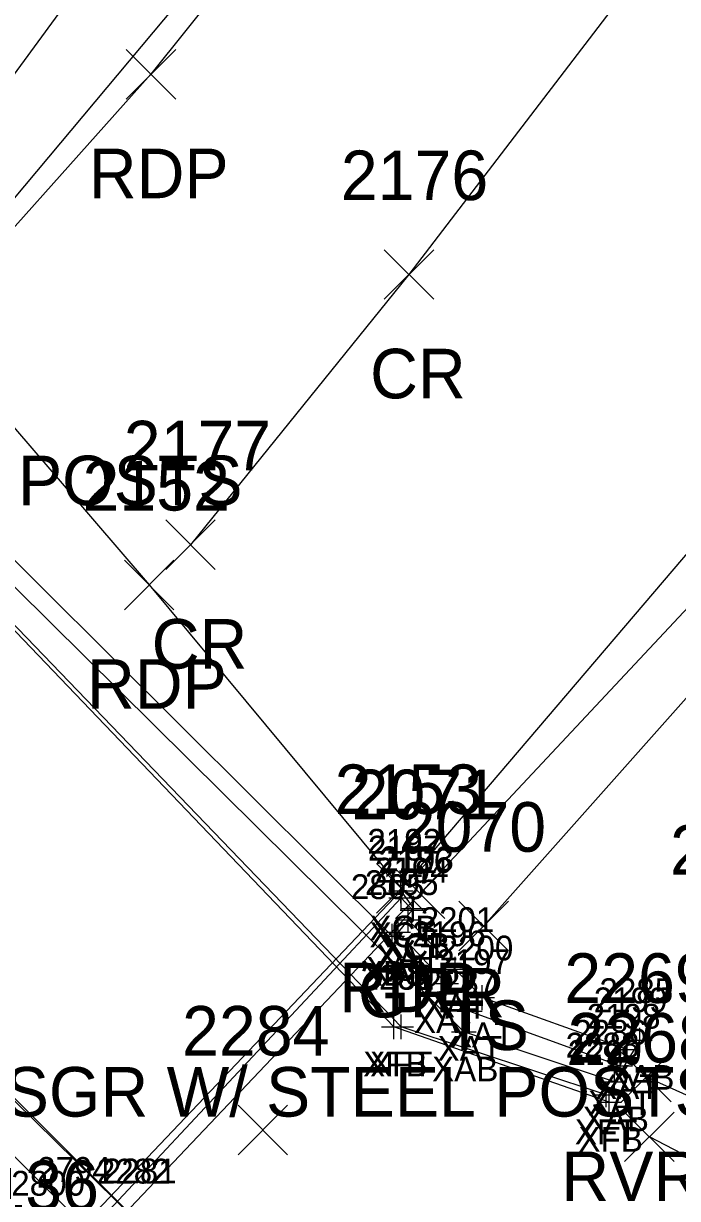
# Model space of a CAD drawing. Extents: x 1633660 to 1636532, y 388643 to 392631.
# Drawn here: x 1634763.61 to 1634790.01, y 389221.92 to 389269.34 of the extents above; entities that cross this region are included whole.
import ezdxf

# ---------------------------------------------------------------- set-up
doc = ezdxf.new("R2010")
doc.units = 0
for name, color, linetype in [('B_A', 7, 'Continuous'), ('B_I', 7, 'Continuous'), ('B_TIC', 7, 'Continuous'), ('BDC', 7, 'Continuous'), ('BFT', 7, 'Continuous'), ('BSE', 7, 'Continuous'), ('BSUBM', 7, 'Continuous'), ('L_A', 7, 'Continuous'), ('L_I', 7, 'Continuous'), ('L_TIC', 7, 'Continuous'), ('LAWE', 7, 'Continuous'), ('LELB', 7, 'Continuous'), ('P_A', 7, 'Continuous'), ('P_I', 7, 'Continuous'), ('P_TIC', 7, 'Continuous'), ('PET', 7, 'Continuous'), ('PRC', 7, 'Continuous'), ('R_A', 7, 'Continuous'), ('R_C', 7, 'Continuous'), ('R_I', 7, 'Continuous'), ('R_TIC', 7, 'Continuous'), ('RGR', 7, 'Continuous')]:
    doc.layers.add(name, color=color, linetype=linetype)

msp = doc.modelspace()

# ---------------------------------------------------------------- linework, layer by layer
at = {"layer": 'B_TIC'}
for p, q in [((1634778.841, 389234.337), (1634778.916, 389234.337)), ((1634778.862, 389234.061), (1634778.937, 389234.061)), ((1634779.315, 389233.554), (1634779.391, 389233.554)), ((1634779.356, 389233.631), (1634779.431, 389233.631)), ((1634779.145, 389233.172), (1634779.221, 389233.172)), ((1634778.496, 389232.505), (1634778.572, 389232.505)), ((1634778.738, 389232.666), (1634778.813, 389232.666)), ((1634781.031, 389231.176), (1634781.107, 389231.176)), ((1634780.673, 389230.603), (1634780.749, 389230.603)), ((1634782.122, 389230.029), (1634782.198, 389230.029)), ((1634781.623, 389229.48), (1634781.699, 389229.48)), ((1634778.565, 389228.852), (1634778.641, 389228.852)), ((1634778.856, 389228.848), (1634778.932, 389228.848)), ((1634781.387, 389228.651), (1634781.462, 389228.651)), ((1634788.493, 389228.309), (1634788.568, 389228.309)), ((1634787.983, 389227.938), (1634788.059, 389227.938)), ((1634787.698, 389227.277), (1634787.774, 389227.277)), ((1634787.465, 389226.63), (1634787.54, 389226.63)), ((1634787.127, 389226.112), (1634787.203, 389226.112)), ((1634787.255, 389225.814), (1634787.33, 389225.814))]:
    msp.add_line(p, q, dxfattribs=at)
for points in [[(1634778.837, 389233.837), (1634778.837, 389234.837)], [(1634778.858, 389233.56), (1634778.858, 389234.561)], [(1634778.337, 389234.337), (1634779.337, 389234.337)], [(1634778.358, 389234.061), (1634779.358, 389234.061)], [(1634779.312, 389233.054), (1634779.312, 389234.054)], [(1634779.352, 389233.131), (1634779.352, 389234.131)], [(1634778.812, 389233.554), (1634779.812, 389233.554)], [(1634778.852, 389233.631), (1634779.852, 389233.631)], [(1634779.142, 389232.672), (1634779.142, 389233.672)], [(1634778.493, 389232.005), (1634778.493, 389233.005)], [(1634778.642, 389233.172), (1634779.642, 389233.172)], [(1634778.734, 389232.166), (1634778.734, 389233.166)], [(1634777.993, 389232.505), (1634778.993, 389232.505)], [(1634778.234, 389232.666), (1634779.234, 389232.666)], [(1634781.028, 389230.676), (1634781.028, 389231.676)], [(1634780.528, 389231.176), (1634781.528, 389231.176)], [(1634780.67, 389230.103), (1634780.67, 389231.103)], [(1634780.17, 389230.603), (1634781.17, 389230.603)], [(1634782.119, 389229.529), (1634782.119, 389230.529)], [(1634781.619, 389230.029), (1634782.619, 389230.029)], [(1634781.62, 389228.98), (1634781.62, 389229.98)], [(1634778.562, 389228.352), (1634778.562, 389229.352)], [(1634778.853, 389228.348), (1634778.853, 389229.348)], [(1634781.12, 389229.48), (1634782.12, 389229.48)], [(1634778.062, 389228.852), (1634779.062, 389228.852)], [(1634778.353, 389228.848), (1634779.353, 389228.848)], [(1634781.383, 389228.151), (1634781.383, 389229.151)], [(1634788.489, 389227.809), (1634788.489, 389228.809)], [(1634780.883, 389228.651), (1634781.883, 389228.651)], [(1634787.98, 389227.438), (1634787.98, 389228.438)], [(1634787.989, 389228.309), (1634788.989, 389228.309)], [(1634787.48, 389227.938), (1634788.48, 389227.938)], [(1634787.695, 389226.777), (1634787.695, 389227.777)], [(1634787.195, 389227.277), (1634788.195, 389227.277)], [(1634787.461, 389226.13), (1634787.461, 389227.13)], [(1634786.961, 389226.63), (1634787.961, 389226.63)], [(1634787.124, 389225.612), (1634787.124, 389226.612)], [(1634786.624, 389226.112), (1634787.624, 389226.112)], [(1634787.251, 389225.314), (1634787.251, 389226.314)], [(1634786.751, 389225.814), (1634787.751, 389225.814)]]:
    msp.add_lwpolyline(points, dxfattribs=at)
at = {"layer": 'BDC'}
for points in [[(1634764.194, 389217.752), (1634763.74, 389218.447), (1634778.837, 389234.337), (1634779.352, 389233.631)], [(1634779.312, 389233.554), (1634778.858, 389234.061), (1634764.163, 389218.344), (1634764.455, 389217.898)], [(1634764.455, 389217.898), (1634779.312, 389233.554)]]:
    msp.add_lwpolyline(points, dxfattribs=at)
at = {"layer": 'BFT'}
for points in [[(1634787.251, 389225.814), (1634778.562, 389228.852), (1634756.719, 389251.654), (1634754.734, 389261.584)], [(1634787.124, 389226.112), (1634778.853, 389228.848), (1634756.842, 389251.699), (1634755.357, 389261.733)], [(1634747.068, 389242.136), (1634768.198, 389221.026)], [(1634746.993, 389241.835), (1634768.161, 389221.033)]]:
    msp.add_lwpolyline(points, dxfattribs=at)
at = {"layer": 'BSE'}
msp.add_lwpolyline([(1634757.888, 389256.912), (1634758.598, 389252.274), (1634778.493, 389232.505)], dxfattribs=at)
at = {"layer": 'BSUBM'}
for points in [[(1634788.489, 389228.309), (1634787.461, 389226.63), (1634781.383, 389228.651), (1634757.708, 389252.066), (1634756.355, 389261.792), (1634750.726, 389271.945), (1634751.561, 389272.556)], [(1634728.916, 389249.02), (1634729.836, 389250.104), (1634742.136, 389242.622), (1634746.673, 389240.04), (1634765.788, 389221.095)], [(1634779.142, 389233.172), (1634778.734, 389232.666), (1634780.67, 389230.603), (1634781.62, 389229.48), (1634787.695, 389227.277), (1634787.98, 389227.938), (1634782.119, 389230.029), (1634781.028, 389231.176)], [(1634781.028, 389231.176), (1634779.142, 389233.172)]]:
    msp.add_lwpolyline(points, dxfattribs=at)
at = {"layer": 'L_TIC'}
for points in [[(1634781.182, 389231.916), (1634783.182, 389233.916)], [(1634783.182, 389231.916), (1634781.182, 389233.916)], [(1634787.756, 389225.818), (1634789.756, 389227.818)], [(1634789.756, 389225.818), (1634787.756, 389227.818)], [(1634772.269, 389223.69), (1634774.269, 389225.69)], [(1634774.269, 389223.69), (1634772.269, 389225.69)], [(1634787.875, 389223.41), (1634789.875, 389225.41)], [(1634789.875, 389223.41), (1634787.875, 389225.41)]]:
    msp.add_lwpolyline(points, dxfattribs=at)
at = {"layer": 'LAWE'}
msp.add_lwpolyline([(1634485.266, 388945.868), (1634504.196, 388941.237), (1634525.532, 388940.734), (1634548.507, 388932.941), (1634584.664, 388919.999), (1634598.752, 388914.409), (1634618.803, 388928.878), (1634638.301, 388944.913), (1634660.99, 388957.079), (1634677.576, 388983.238), (1634696.949, 389006.397), (1634707.364, 389033.308), (1634727.928, 389056.715), (1634749.887, 389078.696), (1634762.92, 389095.064), (1634797.897, 389102.54), (1634816.332, 389112.037), (1634824.178, 389130.773), (1634824.184, 389150.648), (1634818.446, 389174.952), (1634815.049, 389205.919), (1634802.108, 389220.823), (1634788.756, 389226.818)], dxfattribs=at)
at = {"layer": 'LELB'}
for points in [[(1634760.285, 389263.273), (1634777.705, 389287.048), (1634795.737, 389315.603), (1634812.364, 389341.102), (1634834.547, 389376.799), (1634859.6, 389420.587), (1634884.98, 389473.483), (1634914.697, 389519.937)], [(1634830.021, 389262.502), (1634817.023, 389265.015), (1634802.099, 389255.301), (1634782.182, 389232.916)], [(1634633.695, 388947.021), (1634652.585, 388956.595), (1634671.201, 388984.135), (1634685.401, 389000.206), (1634693.628, 389014.81), (1634704.343, 389035.4), (1634725.63, 389062.246), (1634746.904, 389081.237), (1634759.284, 389096.885), (1634788.685, 389102.007), (1634810.124, 389114.596), (1634818.922, 389123.639), (1634818.088, 389148.686), (1634815.048, 389173.408), (1634811.187, 389202.43), (1634801.315, 389217.947), (1634788.875, 389224.41)]]:
    msp.add_lwpolyline(points, dxfattribs=at)
at = {"layer": 'P_TIC'}
for points in [[(1634767.754, 389266.285), (1634769.754, 389268.285)], [(1634769.754, 389266.285), (1634767.754, 389268.285)], [(1634778.167, 389258.209), (1634780.167, 389260.209)], [(1634780.167, 389258.209), (1634778.167, 389260.209)], [(1634769.349, 389247.304), (1634771.349, 389249.304)], [(1634771.349, 389247.304), (1634769.349, 389249.304)], [(1634767.683, 389245.682), (1634769.683, 389247.682)], [(1634769.683, 389245.682), (1634767.683, 389247.682)], [(1634777.862, 389233.437), (1634779.862, 389235.437)], [(1634779.862, 389233.437), (1634777.862, 389235.437)]]:
    msp.add_lwpolyline(points, dxfattribs=at)
at = {"layer": 'PET'}
for points in [[(1634921.002, 389515.03), (1634899.802, 389480.53), (1634874.189, 389437.174), (1634846.922, 389390.201), (1634820.403, 389343.783), (1634802.56, 389312.32), (1634782.667, 389284.651), (1634768.754, 389267.285)], [(1634759.683, 389257.144), (1634768.683, 389246.682), (1634778.862, 389234.437), (1634802.838, 389262.519), (1634835.45, 389312.997), (1634837.672, 389319.49), (1634869.562, 389375.262), (1634896.662, 389421.501), (1634916.947, 389456.153), (1634943.654, 389500.194)], [(1634768.754, 389267.285), (1634759.683, 389257.144)]]:
    msp.add_lwpolyline(points, dxfattribs=at)
at = {"layer": 'PRC'}
msp.add_lwpolyline([(1634932.003, 389507.764), (1634911.044, 389472.797), (1634886.741, 389431.158), (1634857.717, 389381.065), (1634832.11, 389337.094), (1634812.294, 389305.303), (1634793.243, 389277.601), (1634779.167, 389259.209), (1634770.349, 389248.304)], dxfattribs=at)
at = {"layer": 'R_TIC'}
for points in [[(1634778.621, 389233.228), (1634780.621, 389235.228)], [(1634780.621, 389233.228), (1634778.621, 389235.228)]]:
    msp.add_lwpolyline(points, dxfattribs=at)
at = {"layer": 'RGR'}
for points in [[(1634760.391, 389258.897), (1634777.727, 389279.589), (1634802.798, 389315.456), (1634808.813, 389326.626), (1634809.837, 389333.481)], [(1634779.621, 389234.228), (1634797.348, 389253.149), (1634807.413, 389262.179)]]:
    msp.add_lwpolyline(points, dxfattribs=at)

# ---------------------------------------------------------------- texts
at = {"layer": 'B_A'}
for s, p in [('XCB', (1634777.573, 389232.337)), ('XCT', (1634777.579, 389232.061)), ('XCT', (1634778.032, 389231.554)), ('XCB', (1634778.088, 389231.631)), ('XAT', (1634777.847, 389231.172)), ('XAT', (1634777.439, 389230.666)), ('XBS', (1634777.233, 389230.505)), ('XAT', (1634779.733, 389229.176)), ('XAT', (1634779.374, 389228.603)), ('XAT', (1634780.824, 389228.029)), ('XAT', (1634780.324, 389227.48)), ('XFB', (1634777.321, 389226.852)), ('XFT', (1634777.597, 389226.848)), ('XAB', (1634780.104, 389226.651)), ('XAB', (1634787.21, 389226.309)), ('XAT', (1634786.685, 389225.938)), ('XAT', (1634786.399, 389225.277)), ('XAB', (1634786.182, 389224.63)), ('XFT', (1634785.868, 389224.112)), ('XFB', (1634786.011, 389223.814))]:
    msp.add_text(s, height=1, dxfattribs=at).set_placement(p)
at = {"layer": 'B_I'}
for s, p in [('2192', (1634777.491, 389235.837)), ('2187', (1634777.512, 389235.561)), ('2186', (1634777.938, 389235.054)), ('2193', (1634778.006, 389235.131)), ('2194', (1634777.795, 389234.672)), ('2805', (1634776.823, 389234.005)), ('2195', (1634777.388, 389234.166)), ('2201', (1634779.642, 389232.676)), ('2196', (1634779.296, 389232.103)), ('2200', (1634780.406, 389231.529)), ('2197', (1634780.273, 389230.98)), ('2291', (1634777.215, 389230.352)), ('2289', (1634777.219, 389230.348)), ('2287', (1634779.754, 389230.151)), ('2285', (1634786.859, 389229.809)), ('2199', (1634786.63, 389229.438)), ('2198', (1634786.348, 389228.777)), ('2286', (1634785.804, 389228.13)), ('2288', (1634785.494, 389227.612)), ('2290', (1634785.578, 389227.314)), ('2794', (1634764.158, 389222.595)), ('2282', (1634766.568, 389222.526)), ('2281', (1634766.814, 389222.533)), ('2800', (1634763.114, 389222.038))]:
    msp.add_text(s, height=1, dxfattribs=at).set_placement(p)
at = {"layer": 'L_A'}
for s, p in [('TS', (1634780.592, 389227.916)), ('RVRL', (1634785.323, 389221.818))]:
    msp.add_text(s, height=2, dxfattribs=at).set_placement(p)
at = {"layer": 'L_I'}
for s, p in [('2070', (1634778.757, 389235.916)), ('2062', (1634789.708, 389234.987)), ('2269', (1634785.441, 389229.818)), ('2284', (1634770.01, 389227.69)), ('2268', (1634785.568, 389227.41))]:
    msp.add_text(s, height=2, dxfattribs=at).set_placement(p)
at = {"layer": 'P_A'}
for s, p in [('RDP', (1634766.242, 389262.285)), ('CR', (1634777.6, 389254.209)), ('CR', (1634768.782, 389243.304)), ('RDP', (1634766.171, 389241.682)), ('RDP', (1634776.351, 389229.437))]:
    msp.add_text(s, height=2, dxfattribs=at).set_placement(p)
at = {"layer": 'P_I'}
for s, p in [('2176', (1634776.419, 389262.209)), ('2177', (1634767.656, 389251.304)), ('2152', (1634765.99, 389249.682)), ('2153', (1634776.17, 389237.437)), ('2136', (1634760.704, 389221.449))]:
    msp.add_text(s, height=2, dxfattribs=at).set_placement(p)
at = {"layer": 'R_A'}
msp.add_text('GRR', height=2, dxfattribs=at).set_placement((1634777.11, 389229.228))
at = {"layer": 'R_C'}
for p in [(1634743.62, 389249.897), (1634762.85, 389225.228)]:
    msp.add_text('SGR W/ STEEL POSTS', height=2, dxfattribs=at).set_placement(p)
at = {"layer": 'R_I'}
msp.add_text('2071', height=2, dxfattribs=at).set_placement((1634776.85, 389237.228))

doc.saveas('drawing.dxf')
